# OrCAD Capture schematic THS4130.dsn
size A
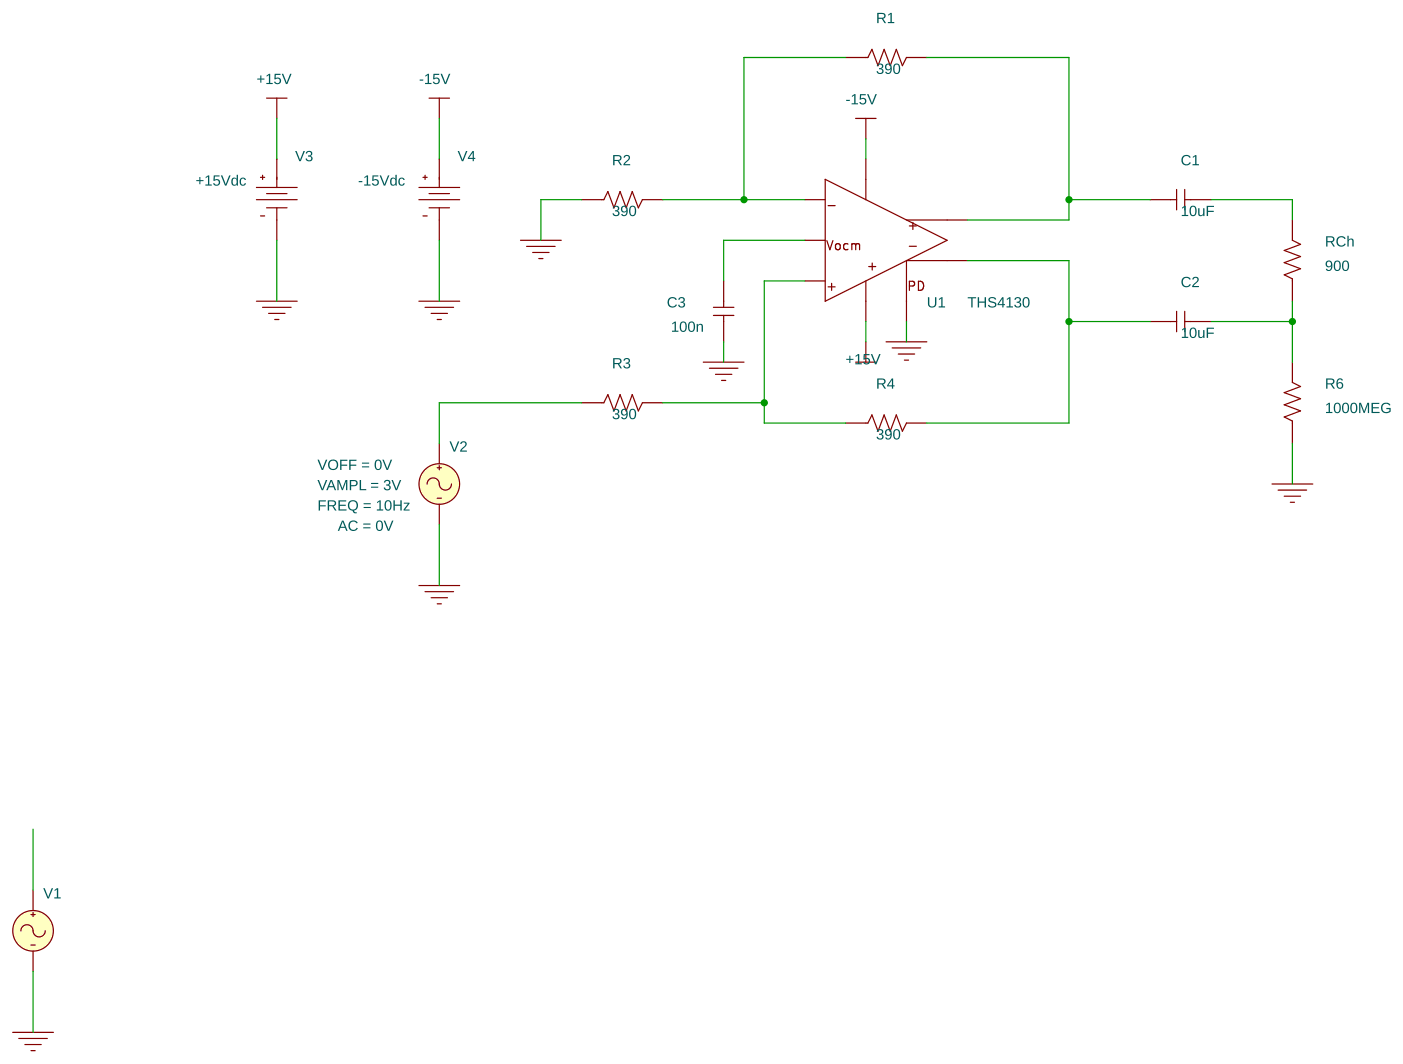
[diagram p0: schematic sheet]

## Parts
C1  10uF  [cap196]
C2  10uF  [cap196]
C3  100n  [cap196]
R1  390  [AXRC05]
R2  390  [AXRC05]
R3  390  [AXRC05]
R4  390  [AXRC05]
R6  1000MEG  [AXRC05]
RCh  900  [AXRC05]
U1  THS4130
V1  VAC
V2  VSIN
V3  VDC
V4  VDC

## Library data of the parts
C1-C3 = C
R1-R4 R6 RCh = R
U1 = THS4130
V1 = VAC
V2 = VSIN: AC: 0V; FREQ: 10Hz; VAMPL: 3V; VOFF: 0V
V3 = VDC: DC: +15Vdc
V4 = VDC: DC: -15Vdc

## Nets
+15V: U1.3 V3.0(+)
-15V: U1.6 V4.0(+)
0: C3.1 R2.1 R6.1 U1.7 V1.2(-) V2.2(-) V3.1(-) V4.1(-)
N14353: C3.2 U1.2
N14434: R3.2 R4.1 U1.8
N14451: C2.1 R4.2 U1.5
N14469: C1.1 R1.2 U1.4
N14481: R1.1 R2.2 U1.1
N14626: C2.2 R6.2 RCh.1
N14635: C1.2 RCh.2
N16421: R3.1 V2.1(+)

Not connected (* = marked no-connect by the designer): V1 1(+)
